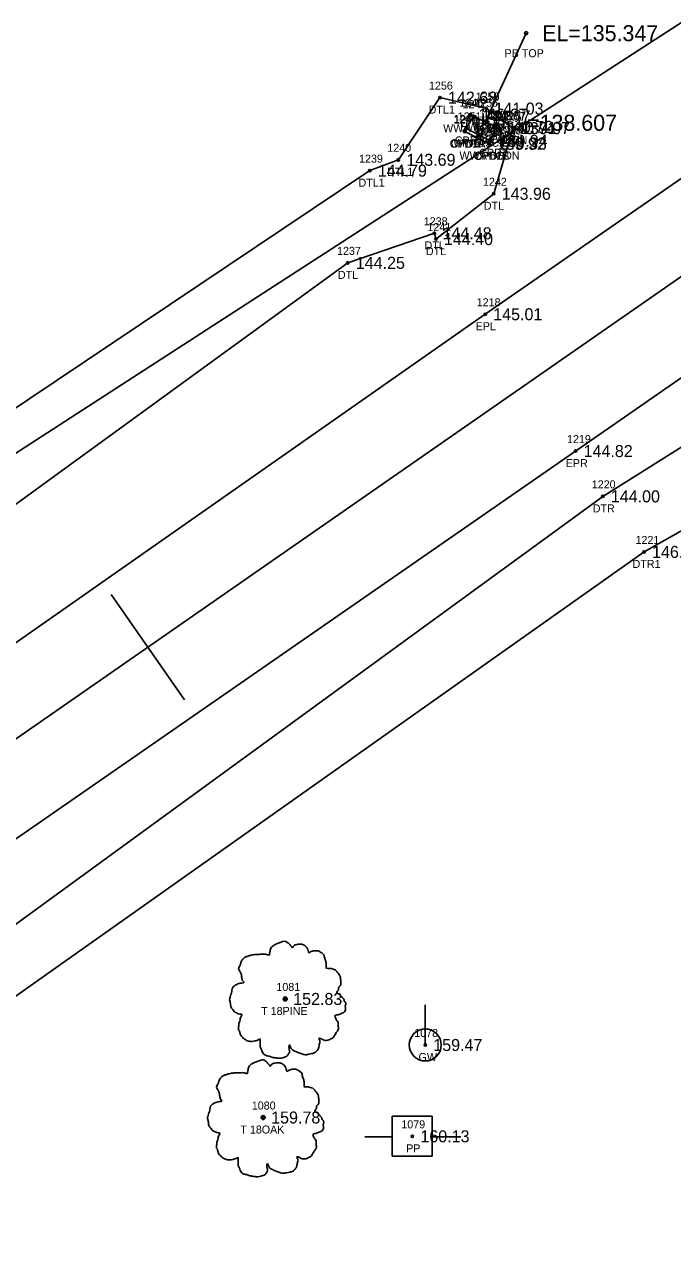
# Model space of a CAD drawing. Extents: x 2449052 to 2452984, y 1012343 to 1015262.
# Drawn here: x 2450676.2 to 2450757.2, y 1013613.6 to 1013766.6 of the extents above; entities that cross this region are included whole.
import ezdxf

# ---------------------------------------------------------------- set-up
doc = ezdxf.new("R2010")
doc.units = 0
for name, color, linetype in [('RD_EX_Bridge', 7, 'Continuous'), ('RD_EX_Bridge_txCode', 7, 'Continuous'), ('RD_EX_Conc', 7, 'Continuous'), ('RD_EX_Conc_txCode', 7, 'Continuous'), ('RD_EX_DR_Pipe', 7, 'Continuous'), ('RD_EX_DR_Pipe_txCode', 7, 'Continuous'), ('RD_EX_H2O', 7, 'Continuous'), ('RD_EX_H2O_txCode', 7, 'Continuous'), ('RD_EX_Road', 7, 'Continuous'), ('RD_EX_Road_txCode', 7, 'Continuous'), ('RD_EX_TX_Bridge_ELEV', 7, 'Continuous'), ('RD_EX_TX_Conc_ELEV', 7, 'Continuous'), ('RD_EX_TX_H2O_ELEV', 7, 'Continuous'), ('RD_EX_TX_Road_ELEV', 7, 'Continuous'), ('RD_EX_TX_UT_ELEV', 7, 'Continuous'), ('RD_EX_TX_VEG_ELEV', 7, 'Continuous'), ('RD_EX_UT', 7, 'Continuous'), ('RD_EX_UT_txCode', 7, 'Continuous'), ('RD_EX_VEG', 7, 'Continuous'), ('RD_EX_VEG_txCode', 7, 'Continuous'), ('RD_HC_Cl', 7, 'Continuous'), ('RD_HC_Data_Tic', 7, 'Continuous'), ('RD_HC_Survey_ELEV', 7, 'Continuous'), ('RD_SMD_Locator', 7, 'Continuous'), ('RD_TX_Pipe_ElevEX', 7, 'Continuous')]:
    doc.layers.add(name, color=color, linetype=linetype)

msp = doc.modelspace()

# ---------------------------------------------------------------- linework, layer by layer
at = {"layer": 'RD_EX_Bridge'}
for p, q in [((2450735.54, 1013753.64), (2450731.94, 1013755.32)), ((2450732.32, 1013755.13), (2450731.19, 1013753.29)), ((2450734.36, 1013751.72), (2450735.14, 1013753.8))]:
    msp.add_line(p, q, dxfattribs=at)
at = {"layer": 'RD_EX_Conc'}
msp.add_line((2450731.24, 1013753.21), (2450734.23, 1013751.68), dxfattribs=at)
msp.add_lwpolyline([(2450731.24, 1013753.21), (2450731.4, 1013753.6), (2450734.45, 1013752.06), (2450734.23, 1013751.68)], dxfattribs=at)
at = {"layer": 'RD_EX_DR_Pipe'}
msp.add_line((2450733.75, 1013754.31), (2450738.9, 1013765.5), dxfattribs=at)
at = {"layer": 'RD_EX_H2O'}
for points in [[(2450611.14, 1013666.87), (2450616.31, 1013679.25), (2450719.37, 1013748.33), (2450722.94, 1013749.68), (2450728.13, 1013757.45), (2450733.94, 1013756.08)], [(2450611.14, 1013666.87), (2450613.78, 1013662.06), (2450716.62, 1013736.81), (2450727.45, 1013740.5), (2450727.63, 1013739.78), (2450734.85, 1013745.44), (2450737.25, 1013753.64), (2450733.94, 1013756.08)], [(2450167.46, 1013291.72), (2450167.1, 1013295.75), (2450175.19, 1013302.21), (2450253.51, 1013357.72), (2450334.87, 1013415.7), (2450415.19, 1013473.64), (2450493.27, 1013528.65), (2450573.99, 1013585.66), (2450651, 1013636.62), (2450748.48, 1013707.64), (2450786.48, 1013731.51)], [(2450167.46, 1013291.72), (2450171.71, 1013290.19), (2450180.8, 1013296.66), (2450259.89, 1013349.14), (2450344.33, 1013402.02), (2450412.23, 1013445.13), (2450424.15, 1013461.12), (2450474.5, 1013497.19), (2450500.92, 1013517.59), (2450581.65, 1013574.66), (2450655.67, 1013631.45), (2450753.63, 1013700.7), (2450792.21, 1013722.47), (2450790.93, 1013725.57), (2450786.48, 1013731.51)]]:
    msp.add_lwpolyline(points, dxfattribs=at)
at = {"layer": 'RD_EX_Road'}
for points in [[(2449674.89, 1012994.69), (2449752.35, 1013048.28), (2449834.92, 1013105.96), (2449914.72, 1013161.11), (2449995.66, 1013217.59), (2450075.29, 1013272.9), (2450081.34, 1013277.24), (2450093.41, 1013285.64), (2450155.49, 1013328.69), (2450236.05, 1013384.7), (2450317.88, 1013441.24), (2450398.87, 1013497.28), (2450477.09, 1013551.76), (2450555.6, 1013606.73), (2450600.18, 1013637.7), (2450618.08, 1013649.65), (2450627.95, 1013656.57), (2450636.43, 1013662.28), (2450733.79, 1013730.39), (2450811.43, 1013784.18), (2450891.39, 1013839.9), (2450907.04, 1013850.14)], [(2449685.94, 1012977.62), (2449764.81, 1013032.3), (2449846, 1013088.39), (2449925.85, 1013144.07), (2450006.8, 1013200.56), (2450086.45, 1013256.14), (2450125.67, 1013283.43), (2450163.55, 1013309.93), (2450166.36, 1013312.09), (2450247.44, 1013367.98), (2450329.19, 1013424.41), (2450410.32, 1013481.09), (2450488.38, 1013535.38), (2450567.5, 1013590.14), (2450648.09, 1013646.13), (2450745.08, 1013713.3), (2450823, 1013767.39), (2450902.19, 1013823.2), (2450918.14, 1013833.95)]]:
    msp.add_lwpolyline(points, dxfattribs=at)
at = {"layer": 'RD_EX_UT'}
for p, q in [((2450726.3, 1013639.11), (2450726.3, 1013644.11)), ((2450727.18, 1013630.21), (2450722.18, 1013630.21)), ((2450722.18, 1013630.21), (2450722.18, 1013625.21)), ((2450727.18, 1013625.21), (2450727.18, 1013630.21)), ((2450718.75, 1013627.65), (2450722.22, 1013627.65)), ((2450727.11, 1013627.65), (2450730.75, 1013627.65)), ((2450722.18, 1013625.21), (2450727.18, 1013625.21))]:
    msp.add_line(p, q, dxfattribs=at)
msp.add_circle((2450726.3, 1013639.11), 2, dxfattribs=at)
at = {"layer": 'RD_EX_VEG'}
msp.add_lwpolyline([(2450511.25, 1013744.81), (2450612.22, 1013672.34), (2450883.9, 1013848.07), (2451091.43, 1014003.45), (2451271.45, 1014121.26), (2451583.45, 1014347.48), (2451819.08, 1014511.44), (2452219.54, 1014796.6), (2452332.78, 1014867.52)], dxfattribs=at)
for centre, radius in [((2450708.8, 1013644.86), 0.25), ((2450708.79, 1013644.85), 0.0001), ((2450706.05, 1013630.05), 0.25), ((2450706.04, 1013630.03), 0.0001)]:
    msp.add_circle(centre, radius, dxfattribs=at)
for points in [[(2450708.94, 1013652.03), (2450708.64, 1013652.06), (2450708.31, 1013651.96), (2450708.06, 1013651.86), (2450707.84, 1013651.78), (2450707.61, 1013651.68), (2450707.31, 1013651.51), (2450707.09, 1013651.31), (2450706.96, 1013651.06), (2450706.91, 1013650.83), (2450706.86, 1013650.56), (2450706.86, 1013650.38), (2450706.74, 1013650.36), (2450706.59, 1013650.38), (2450706.34, 1013650.46), (2450706.09, 1013650.46), (2450705.84, 1013650.46), (2450705.49, 1013650.43), (2450705.14, 1013650.43), (2450704.86, 1013650.38), (2450704.54, 1013650.33), (2450704.16, 1013650.21), (2450703.81, 1013650.08), (2450703.51, 1013649.83), (2450703.26, 1013649.36), (2450703.14, 1013649.01), (2450702.99, 1013648.76), (2450703.14, 1013648.31), (2450703.31, 1013647.96), (2450703.34, 1013647.76), (2450703.41, 1013647.33), (2450703.51, 1013647.11), (2450703.64, 1013646.91), (2450703.56, 1013646.88), (2450703.19, 1013646.83), (2450702.89, 1013646.73), (2450702.46, 1013646.51), (2450702.24, 1013646.28), (2450702.14, 1013645.96), (2450702.11, 1013645.61), (2450702.01, 1013645.41), (2450701.94, 1013645.13), (2450701.91, 1013645.06), (2450701.86, 1013644.73), (2450701.96, 1013644.28), (2450701.99, 1013643.94), (2450702.11, 1013643.71), (2450702.26, 1013643.54), (2450702.44, 1013643.29), (2450702.84, 1013643.06), (2450703.16, 1013642.96), (2450703.36, 1013642.94), (2450703.19, 1013642.44), (2450703.14, 1013642.09), (2450703.01, 1013641.69), (2450703.01, 1013641.61), (2450702.96, 1013641.14), (2450703.11, 1013640.81), (2450703.19, 1013640.44), (2450703.36, 1013640.21), (2450703.64, 1013639.91), (2450703.96, 1013639.69), (2450704.46, 1013639.56), (2450704.86, 1013639.59), (2450705.44, 1013639.76), (2450705.69, 1013639.84), (2450705.66, 1013639.66), (2450705.69, 1013639.29), (2450705.69, 1013638.86), (2450705.84, 1013638.54), (2450705.94, 1013638.26), (2450706.09, 1013638.01), (2450706.41, 1013637.79), (2450706.81, 1013637.71), (2450707.24, 1013637.56), (2450707.69, 1013637.49), (2450708.19, 1013637.46), (2450708.79, 1013637.61), (2450709.06, 1013637.74), (2450709.16, 1013637.91), (2450709.36, 1013638.29), (2450709.31, 1013638.51), (2450709.34, 1013639.11), (2450709.44, 1013638.94), (2450709.61, 1013638.59), (2450710.11, 1013638.29), (2450710.51, 1013638.11), (2450710.99, 1013637.96), (2450711.29, 1013637.89), (2450711.76, 1013637.96), (2450712.13, 1013638.04), (2450712.51, 1013638.16), (2450712.81, 1013638.44), (2450712.98, 1013638.71), (2450713.03, 1013638.99), (2450713.11, 1013639.36), (2450713.16, 1013639.54)], [(2450713.16, 1013639.54), (2450713.08, 1013639.71), (2450713.03, 1013639.96), (2450713.11, 1013639.94), (2450713.28, 1013639.89), (2450713.56, 1013639.76), (2450713.78, 1013639.69), (2450714.11, 1013639.71), (2450714.38, 1013639.81), (2450714.83, 1013640.09), (2450715.11, 1013640.56), (2450715.38, 1013640.96), (2450715.46, 1013641.29), (2450715.41, 1013641.51), (2450715.38, 1013642.01), (2450715.18, 1013642.26), (2450715.13, 1013642.39), (2450715.03, 1013642.79), (2450715.11, 1013642.84), (2450715.38, 1013642.89), (2450715.76, 1013643.01), (2450716.03, 1013643.14), (2450716.26, 1013643.31), (2450716.33, 1013643.54), (2450716.31, 1013643.94), (2450716.36, 1013644.33), (2450716.28, 1013644.48), (2450716.18, 1013644.63), (2450716.11, 1013644.83), (2450715.96, 1013644.98), (2450715.86, 1013645.13), (2450715.76, 1013645.23), (2450715.63, 1013645.38), (2450715.46, 1013645.51), (2450715.31, 1013645.56), (2450715.26, 1013645.71), (2450715.41, 1013645.91), (2450715.46, 1013646.01), (2450715.48, 1013646.23), (2450715.71, 1013646.58), (2450715.76, 1013646.98), (2450715.71, 1013647.41), (2450715.66, 1013647.68), (2450715.51, 1013647.96), (2450715.31, 1013648.21), (2450715.18, 1013648.38), (2450715.01, 1013648.51), (2450714.68, 1013648.63), (2450714.43, 1013648.68), (2450714.08, 1013648.68), (2450713.88, 1013648.73), (2450713.91, 1013648.78), (2450713.91, 1013648.93), (2450713.91, 1013649.21), (2450713.83, 1013649.66), (2450713.68, 1013650.16), (2450713.68, 1013650.18), (2450713.58, 1013650.43), (2450713.36, 1013650.63), (2450713.18, 1013650.73), (2450712.98, 1013650.86), (2450712.73, 1013650.88), (2450712.43, 1013650.88), (2450712.16, 1013650.83), (2450711.96, 1013650.73), (2450711.79, 1013650.61), (2450711.71, 1013650.76), (2450711.61, 1013651.06), (2450711.56, 1013651.21), (2450711.41, 1013651.38), (2450711.19, 1013651.58), (2450710.74, 1013651.71), (2450710.11, 1013651.63), (2450709.81, 1013651.43), (2450709.66, 1013651.26), (2450709.61, 1013651.38), (2450709.41, 1013651.58), (2450709.31, 1013651.76), (2450709.14, 1013651.88), (2450708.99, 1013651.98), (2450708.89, 1013652.03)], [(2450706.19, 1013637.22), (2450705.89, 1013637.24), (2450705.56, 1013637.14), (2450705.31, 1013637.04), (2450705.09, 1013636.97), (2450704.86, 1013636.87), (2450704.56, 1013636.7), (2450704.34, 1013636.5), (2450704.21, 1013636.25), (2450704.16, 1013636.02), (2450704.11, 1013635.75), (2450704.11, 1013635.57), (2450703.99, 1013635.55), (2450703.84, 1013635.57), (2450703.59, 1013635.65), (2450703.34, 1013635.65), (2450703.09, 1013635.65), (2450702.74, 1013635.62), (2450702.39, 1013635.62), (2450702.11, 1013635.57), (2450701.79, 1013635.52), (2450701.41, 1013635.4), (2450701.06, 1013635.27), (2450700.76, 1013635.02), (2450700.51, 1013634.55), (2450700.39, 1013634.2), (2450700.24, 1013633.95), (2450700.39, 1013633.5), (2450700.56, 1013633.15), (2450700.59, 1013632.95), (2450700.66, 1013632.52), (2450700.76, 1013632.3), (2450700.89, 1013632.1), (2450700.81, 1013632.07), (2450700.44, 1013632.02), (2450700.14, 1013631.92), (2450699.71, 1013631.7), (2450699.49, 1013631.47), (2450699.39, 1013631.15), (2450699.36, 1013630.8), (2450699.26, 1013630.6), (2450699.19, 1013630.32), (2450699.16, 1013630.25), (2450699.11, 1013629.92), (2450699.21, 1013629.47), (2450699.24, 1013629.12), (2450699.36, 1013628.9), (2450699.51, 1013628.72), (2450699.69, 1013628.47), (2450700.09, 1013628.25), (2450700.41, 1013628.15), (2450700.61, 1013628.12), (2450700.44, 1013627.62), (2450700.39, 1013627.27), (2450700.26, 1013626.87), (2450700.26, 1013626.8), (2450700.21, 1013626.32), (2450700.36, 1013626), (2450700.44, 1013625.62), (2450700.61, 1013625.4), (2450700.89, 1013625.1), (2450701.21, 1013624.88), (2450701.71, 1013624.75), (2450702.11, 1013624.78), (2450702.69, 1013624.95), (2450702.94, 1013625.03), (2450702.91, 1013624.85), (2450702.94, 1013624.48), (2450702.94, 1013624.05), (2450703.09, 1013623.73), (2450703.19, 1013623.45), (2450703.34, 1013623.2), (2450703.66, 1013622.98), (2450704.06, 1013622.9), (2450704.49, 1013622.75), (2450704.94, 1013622.68), (2450705.44, 1013622.65), (2450706.04, 1013622.8), (2450706.31, 1013622.93), (2450706.41, 1013623.1), (2450706.61, 1013623.48), (2450706.56, 1013623.7), (2450706.58, 1013624.3), (2450706.68, 1013624.13), (2450706.86, 1013623.78), (2450707.36, 1013623.48), (2450707.76, 1013623.3), (2450708.23, 1013623.15), (2450708.53, 1013623.08), (2450709.01, 1013623.15), (2450709.38, 1013623.23), (2450709.76, 1013623.35), (2450710.06, 1013623.63), (2450710.23, 1013623.9), (2450710.28, 1013624.18), (2450710.36, 1013624.55), (2450710.41, 1013624.73)], [(2450710.41, 1013624.73), (2450710.33, 1013624.9), (2450710.28, 1013625.15), (2450710.36, 1013625.13), (2450710.53, 1013625.08), (2450710.81, 1013624.95), (2450711.03, 1013624.88), (2450711.36, 1013624.9), (2450711.63, 1013625), (2450712.08, 1013625.28), (2450712.36, 1013625.75), (2450712.63, 1013626.15), (2450712.71, 1013626.47), (2450712.66, 1013626.7), (2450712.63, 1013627.2), (2450712.43, 1013627.45), (2450712.38, 1013627.57), (2450712.28, 1013627.97), (2450712.36, 1013628.02), (2450712.63, 1013628.07), (2450713.01, 1013628.2), (2450713.28, 1013628.32), (2450713.51, 1013628.5), (2450713.58, 1013628.72), (2450713.56, 1013629.12), (2450713.61, 1013629.52), (2450713.53, 1013629.67), (2450713.43, 1013629.82), (2450713.36, 1013630.02), (2450713.21, 1013630.17), (2450713.11, 1013630.32), (2450713.01, 1013630.42), (2450712.88, 1013630.57), (2450712.71, 1013630.7), (2450712.56, 1013630.75), (2450712.51, 1013630.9), (2450712.66, 1013631.1), (2450712.71, 1013631.2), (2450712.73, 1013631.42), (2450712.96, 1013631.77), (2450713.01, 1013632.17), (2450712.96, 1013632.6), (2450712.91, 1013632.87), (2450712.76, 1013633.15), (2450712.56, 1013633.4), (2450712.43, 1013633.57), (2450712.26, 1013633.7), (2450711.93, 1013633.82), (2450711.68, 1013633.87), (2450711.33, 1013633.87), (2450711.13, 1013633.92), (2450711.16, 1013633.97), (2450711.16, 1013634.12), (2450711.16, 1013634.4), (2450711.08, 1013634.85), (2450710.93, 1013635.35), (2450710.93, 1013635.37), (2450710.83, 1013635.62), (2450710.61, 1013635.82), (2450710.43, 1013635.92), (2450710.23, 1013636.05), (2450709.98, 1013636.07), (2450709.68, 1013636.07), (2450709.41, 1013636.02), (2450709.21, 1013635.92), (2450709.03, 1013635.8), (2450708.96, 1013635.95), (2450708.86, 1013636.25), (2450708.81, 1013636.4), (2450708.66, 1013636.57), (2450708.43, 1013636.77), (2450707.98, 1013636.89), (2450707.36, 1013636.82), (2450707.06, 1013636.62), (2450706.91, 1013636.45), (2450706.86, 1013636.57), (2450706.66, 1013636.77), (2450706.56, 1013636.94), (2450706.39, 1013637.07), (2450706.24, 1013637.17), (2450706.14, 1013637.22)]]:
    msp.add_spline(points, degree=3, dxfattribs=at)
at = {"layer": 'RD_HC_Cl'}
msp.add_line((2449680.91, 1012986.23), (2452350.19, 1014841.68), dxfattribs=at)
at = {"layer": 'RD_HC_Data_Tic'}
for q in [(2450687.07, 1013695.37), (2450696.21, 1013682.23)]:
    msp.add_line((2450691.64, 1013688.8), q, dxfattribs=at)
at = {"layer": 'RD_SMD_Locator'}
for centre, radius in [((2450738.9, 1013765.5), 0.2), ((2450728.13, 1013757.45), 0.15), ((2450731.94, 1013755.32), 0.15), ((2450732.32, 1013755.13), 0.15), ((2450733.94, 1013756.08), 0.15), ((2450733.94, 1013756.08), 0.15), ((2450731.4, 1013753.6), 0.15), ((2450733.75, 1013754.31), 0.2), ((2450735.14, 1013753.8), 0.15), ((2450735.54, 1013753.64), 0.15), ((2450737.25, 1013753.64), 0.15), ((2450731.19, 1013753.29), 0.15), ((2450731.24, 1013753.21), 0.15), ((2450731.24, 1013753.21), 0.15), ((2450734.45, 1013752.06), 0.15), ((2450734.23, 1013751.68), 0.15), ((2450734.23, 1013751.68), 0.15), ((2450734.36, 1013751.72), 0.15), ((2450722.94, 1013749.68), 0.15), ((2450719.37, 1013748.33), 0.15), ((2450734.85, 1013745.44), 0.15), ((2450727.45, 1013740.5), 0.15), ((2450727.63, 1013739.78), 0.15), ((2450716.62, 1013736.81), 0.15), ((2450733.79, 1013730.39), 0.15), ((2450745.08, 1013713.3), 0.15), ((2450748.48, 1013707.64), 0.15), ((2450753.63, 1013700.7), 0.15), ((2450708.8, 1013644.86), 0.15), ((2450726.3, 1013639.11), 0.15), ((2450706.05, 1013630.05), 0.15), ((2450724.69, 1013627.7), 0.15)]:
    msp.add_circle(centre, radius, dxfattribs=at)

# ---------------------------------------------------------------- texts
at = {"layer": 'RD_EX_Bridge_txCode'}
for s, p in [('1246', (2450730.57, 1013756.32)), ('1247', (2450730.97, 1013756.13)), ('1248', (2450729.84, 1013754.29)), ('1244', (2450733.8, 1013754.8)), ('1245', (2450734.19, 1013754.64)), ('WWA 6CON', (2450728.53, 1013753.13)), ('HWB', (2450730.65, 1013753.32)), ('1243', (2450733.01, 1013752.72)), ('WWB', (2450729.81, 1013751.29)), ('HWA 6CON', (2450731.84, 1013751.64)), ('WWB', (2450733.77, 1013751.8)), ('WWA 6CON', (2450730.57, 1013749.72))]:
    msp.add_text(s, height=1, dxfattribs=at).set_placement(p)
at = {"layer": 'RD_EX_Conc_txCode'}
for s, p in [('1251', (2450730.34, 1013754.6)), ('1250', (2450729.86, 1013754.21)), ('1249', (2450729.9, 1013754.21)), ('1252', (2450733.1, 1013753.06)), ('CPD1A', (2450729.34, 1013751.21)), ('CPDA', (2450729.5, 1013751.21)), ('CPD1', (2450729.99, 1013751.6)), ('1253', (2450732.88, 1013752.68)), ('1254', (2450732.88, 1013752.68)), ('CPD1B', (2450732.34, 1013749.68)), ('CPDB', (2450732.5, 1013749.68)), ('CPD1', (2450733.03, 1013750.06))]:
    msp.add_text(s, height=1, dxfattribs=at).set_placement(p)
at = {"layer": 'RD_EX_DR_Pipe_txCode'}
for s, p in [('PB TOP', (2450736.2, 1013762.5)), ('1255', (2450732.41, 1013756.31)), ('PA 15CP', (2450730.91, 1013751.31))]:
    msp.add_text(s, height=1, dxfattribs=at).set_placement(p)
at = {"layer": 'RD_EX_H2O_txCode'}
for s, p in [('1256', (2450726.76, 1013758.45)), ('1258', (2450732.59, 1013757.08)), ('1259', (2450732.59, 1013757.08)), ('DTL1', (2450726.72, 1013755.45)), ('1257', (2450735.91, 1013754.64)), ('DTL1B', (2450732.06, 1013754.08)), ('DTLB', (2450732.22, 1013754.08)), ('DTL', (2450736.01, 1013751.64)), ('1240', (2450721.56, 1013750.68)), ('1239', (2450718.03, 1013749.33)), ('DTL1', (2450721.53, 1013747.68)), ('DTL1', (2450717.96, 1013746.33)), ('1242', (2450733.51, 1013746.44)), ('DTL', (2450733.61, 1013743.44)), ('1238', (2450726.11, 1013741.5)), ('1241', (2450726.56, 1013740.78)), ('1237', (2450715.28, 1013737.81)), ('DTL', (2450726.21, 1013738.5)), ('DTL', (2450726.38, 1013737.78)), ('DTL', (2450715.38, 1013734.81)), ('1220', (2450747.1, 1013708.64)), ('DTR', (2450747.22, 1013705.64)), ('1221', (2450752.57, 1013701.7)), ('DTR1', (2450752.2, 1013698.7))]:
    msp.add_text(s, height=1, dxfattribs=at).set_placement(p)
at = {"layer": 'RD_EX_Road_txCode'}
for s, p in [('1218', (2450732.73, 1013731.39)), ('EPL', (2450732.59, 1013728.39)), ('1219', (2450744.01, 1013714.3)), ('EPR', (2450743.85, 1013711.3))]:
    msp.add_text(s, height=1, dxfattribs=at).set_placement(p)
at = {"layer": 'RD_EX_TX_Bridge_ELEV'}
for s, p in [('140.67', (2450732.94, 1013754.57)), ('140.67', (2450733.32, 1013754.38)), ('140.08', (2450732.19, 1013752.54)), ('140.72', (2450736.14, 1013753.05)), ('140.71', (2450736.54, 1013752.89)), ('140.33', (2450735.36, 1013750.97))]:
    msp.add_text(s, height=1.5, dxfattribs=at).set_placement(p)
at = {"layer": 'RD_EX_TX_Conc_ELEV'}
for s, p in [('139.74', (2450732.24, 1013752.46)), ('139.74', (2450732.24, 1013752.46)), ('139.86', (2450732.4, 1013752.85)), ('139.92', (2450735.23, 1013750.93)), ('139.92', (2450735.23, 1013750.93)), ('139.94', (2450735.45, 1013751.31))]:
    msp.add_text(s, height=1.5, dxfattribs=at).set_placement(p)
at = {"layer": 'RD_EX_TX_H2O_ELEV'}
for s, p in [('142.68', (2450729.13, 1013756.7)), ('141.03', (2450734.94, 1013755.33)), ('141.03', (2450734.94, 1013755.33)), ('139.07', (2450738.25, 1013752.89)), ('143.69', (2450723.94, 1013748.93)), ('144.79', (2450720.37, 1013747.58)), ('143.96', (2450735.85, 1013744.69)), ('144.48', (2450728.45, 1013739.75)), ('144.40', (2450728.63, 1013739.03)), ('144.25', (2450717.62, 1013736.06)), ('144.00', (2450749.48, 1013706.89)), ('146.07', (2450754.63, 1013699.95))]:
    msp.add_text(s, height=1.5, dxfattribs=at).set_placement(p)
at = {"layer": 'RD_EX_TX_Road_ELEV'}
for s, p in [('145.01', (2450734.79, 1013729.64)), ('144.82', (2450746.08, 1013712.55))]:
    msp.add_text(s, height=1.5, dxfattribs=at).set_placement(p)
at = {"layer": 'RD_EX_TX_UT_ELEV'}
msp.add_text('159.47', height=1.5, dxfattribs=at).set_placement((2450727.3, 1013638.36))
at = {"layer": 'RD_EX_TX_VEG_ELEV'}
for s, p in [('152.83', (2450709.8, 1013644.11)), ('159.78', (2450707.05, 1013629.3))]:
    msp.add_text(s, height=1.5, dxfattribs=at).set_placement(p)
at = {"layer": 'RD_EX_UT_txCode'}
for s, p in [('1078', (2450724.92, 1013640.11)), ('GW', (2450725.46, 1013637.11)), ('1079', (2450723.31, 1013628.7)), ('PP', (2450723.91, 1013625.7))]:
    msp.add_text(s, height=1, dxfattribs=at).set_placement(p)
at = {"layer": 'RD_EX_VEG_txCode'}
for s, p in [('1081', (2450707.7, 1013645.86)), ('T 18PINE', (2450705.8, 1013642.86)), ('1080', (2450704.63, 1013631.05)), ('T 18OAK', (2450703.2, 1013628.05))]:
    msp.add_text(s, height=1, dxfattribs=at).set_placement(p)
at = {"layer": 'RD_HC_Survey_ELEV'}
msp.add_text('160.13', height=1.5, dxfattribs=at).set_placement((2450725.69, 1013626.95))
at = {"layer": 'RD_TX_Pipe_ElevEX'}
for s, p in [('EL=135.347', (2450740.9, 1013764.5)), ('EL=138.607', (2450735.75, 1013753.31))]:
    msp.add_text(s, height=2, dxfattribs=at).set_placement(p)

doc.saveas('drawing.dxf')
